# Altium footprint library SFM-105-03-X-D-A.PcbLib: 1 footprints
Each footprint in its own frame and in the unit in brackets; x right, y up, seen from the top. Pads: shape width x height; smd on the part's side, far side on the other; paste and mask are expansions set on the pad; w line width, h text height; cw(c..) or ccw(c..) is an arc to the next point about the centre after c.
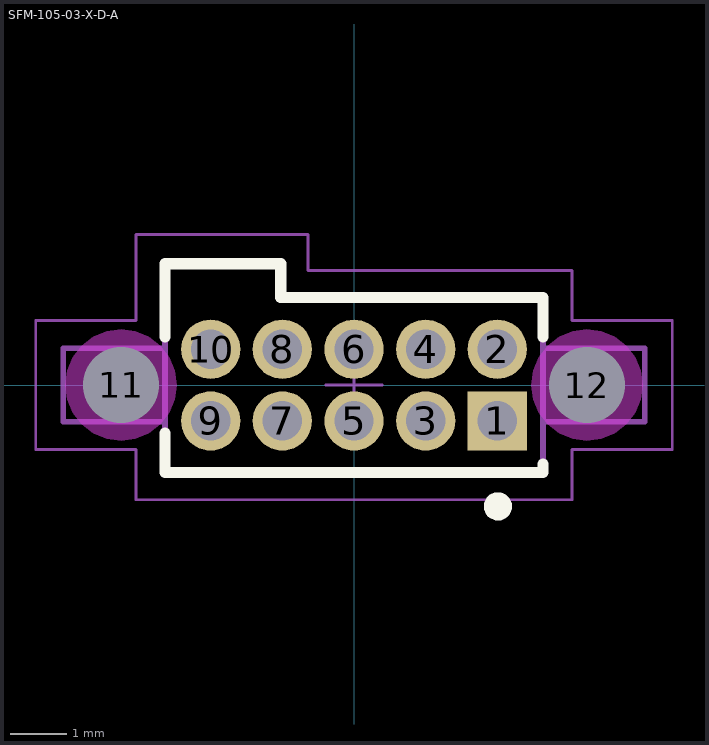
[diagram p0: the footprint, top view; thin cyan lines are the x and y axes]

## SFM-105-03-X-D-A [mm] "1.27mm pitch, 10 pin, socket strip; alignment pins, PTH"
height 4.57
pads (12):
  rect 1.05x1.05 / inner round 1.05 / far side rect 1.05x1.05 hole 0.7 mask+0: 1(2.54,-0.635)
  round 1.05 hole 0.7 mask+0: 2(2.54,0.635) 3(1.27,-0.635) 4(1.27,0.635) 5(0,-0.635) 6(0,0.635) 7(-1.27,-0.635) 8(-1.27,0.635) 9(-2.54,-0.635) 10(-2.54,0.635)
  round 1 hole 1.35 unplated mask+0: 11(-4.127,0) 12(4.127,0)
Top Overlay:
  circle w0.25: c2.55,-2.15 r0.125
  lines w0.2: -3.35,-0.85 -3.35,-1.55 3.35,-1.55 3.35,-1.4 ; -3.35,0.85 -3.35,2.15 -1.3,2.15 -1.3,1.55 3.35,1.55 3.35,0.85
Keep-Out Layer:
  pour cut-out: 5.114,0 5.08,0.255 4.982,0.493 4.825,0.697 4.621,0.854 4.383,0.952 4.128,0.986 3.872,0.952 3.635,0.854 3.43,0.697 3.274,0.493 3.175,0.255 3.142,0 3.175,-0.255 3.274,-0.493 3.43,-0.697 3.635,-0.854 3.872,-0.952 4.128,-0.986 4.383,-0.952 4.621,-0.854 4.825,-0.697 4.982,-0.493 5.08,-0.255
  pour cut-out: -3.142,0 -3.175,0.255 -3.274,0.493 -3.43,0.697 -3.635,0.854 -3.872,0.952 -4.128,0.986 -4.383,0.952 -4.621,0.854 -4.825,0.697 -4.982,0.493 -5.08,0.255 -5.114,0 -5.08,-0.255 -4.982,-0.493 -4.825,-0.697 -4.621,-0.854 -4.383,-0.952 -4.128,-0.986 -3.872,-0.952 -3.635,-0.854 -3.43,-0.697 -3.274,-0.493 -3.175,-0.255
Mechanical 12:
  lines w0.001: -5.15,-0.65 -3.35,-0.65 -3.35,-1.55 3.35,-1.55 3.35,-0.65 5.15,-0.65 5.15,0.65 3.35,0.65 3.35,1.55 -1.3,1.55 -1.3,2.15 -3.35,2.15 -3.35,0.65 -5.15,0.65 -5.15,-0.65
Mechanical 13:
  lines w0.1: -3.353,-0.65 -5.15,-0.65 -5.15,0.65 -3.353,0.65 ; 3.353,-0.65 5.15,-0.65 5.15,0.65 3.353,0.65 ; -3.35,-1.55 3.35,-1.55 3.35,1.55 -1.3,1.55 -1.3,2.15 -3.35,2.15 -3.35,-1.55
  text ".Designator" at 0,-0.127 h1.52
Mechanical 15:
  lines w0.05: -0.5,0 0.5,0 ; 0,-0.5 0,0.5 ; -5.639,-1.143 -3.861,-1.143 -3.861,-2.032 3.861,-2.032 3.861,-1.143 5.639,-1.143 5.639,1.143 3.861,1.143 3.861,2.032 -0.813,2.032 -0.813,2.667 -3.861,2.667 -3.861,1.143 -5.639,1.143 -5.639,-1.143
